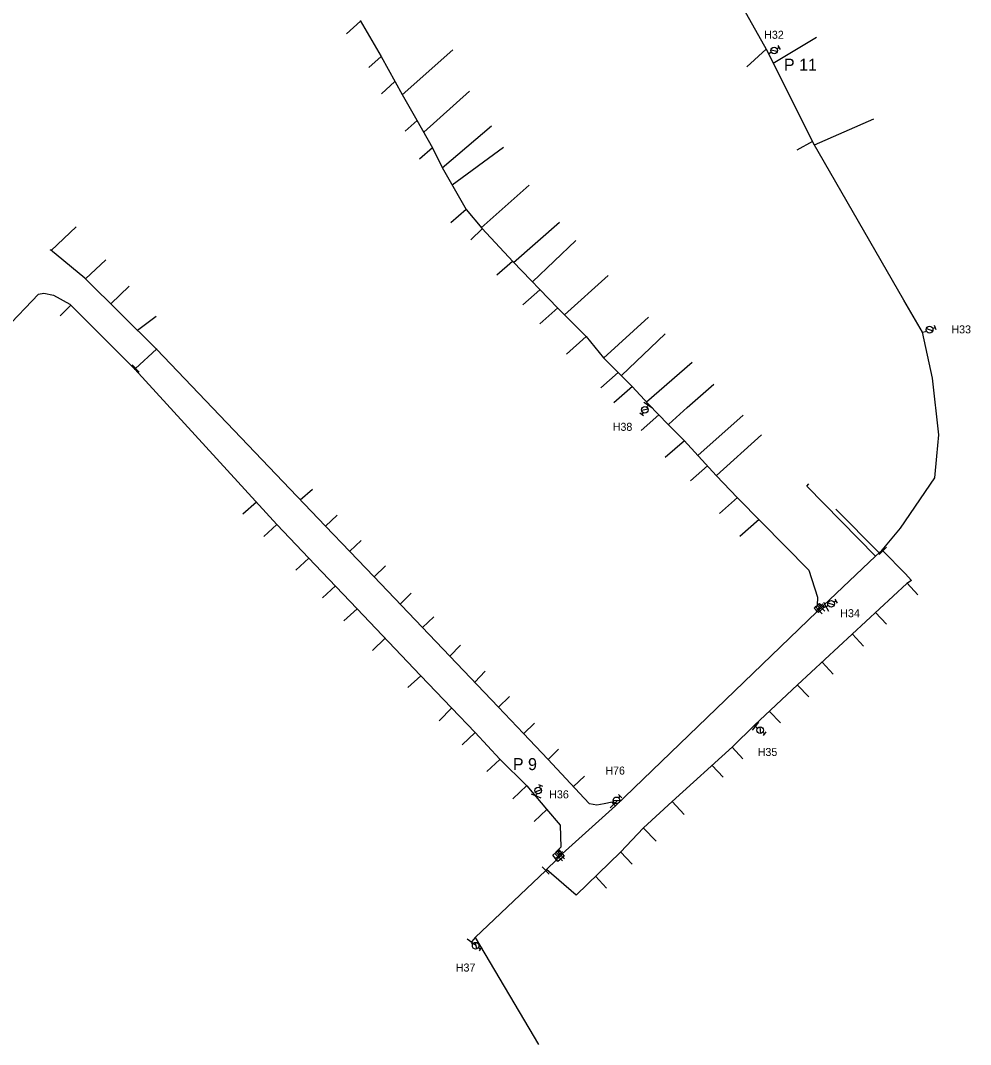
# Model space of a CAD drawing. Extents: x -548873 to -538270, y -1201997 to -1192514.
# Drawn here: x -547306.8 to -547069.3, y -1196073.9 to -1195818 of the extents above; entities that cross this region are included whole.
import ezdxf

# ---------------------------------------------------------------- set-up
doc = ezdxf.new("R2010")
doc.units = 0
for name, color, linetype in [('KN_HRAN_STÁTNÍ', 7, 'Continuous'), ('KN_PARC_Č', 7, 'Continuous'), ('KN_VKP_HRAN_SPORNÁ', 7, 'Continuous'), ('PK_PARC_Čv', 7, 'Continuous'), ('Vrstva 29', 7, 'Continuous'), ('Vrstva 39', 7, 'Continuous')]:
    doc.layers.add(name, color=color, linetype=linetype)

# ---------------------------------------------------------------- blocks, each defined once
blk = doc.blocks.new('147')
at = {"layer": 'KN_HRAN_STÁTNÍ'}
blk.add_line((0, 1.27), (0, -1.27), dxfattribs=at)
blk = doc.blocks.new('160')
at = {"layer": 'KN_HRAN_STÁTNÍ'}
blk.add_circle((0, 0), 0.0458, dxfattribs=at)
blk = doc.blocks.new('133')
at = {"layer": 'KN_HRAN_STÁTNÍ'}
for p, q in [((0.28, 0), (0, 0)), ((0.54, 0.58), (1.7, -0.58)), ((1.94, 0), (2.52, 0)), ((2.52, 0.58), (2.52, -0.58))]:
    blk.add_line(p, q, dxfattribs=at)
blk.add_circle((1.11, 0), 0.825, dxfattribs=at)
blk = doc.blocks.new('150')
at = {"layer": 'KN_HRAN_STÁTNÍ'}
blk.add_line((0, 1.27), (0, -1.27), dxfattribs=at)
blk = doc.blocks.new('124')
at = {"layer": 'KN_HRAN_STÁTNÍ'}
for q in [(-0.19, 1.22), (-0.19, 0.92), (0.19, 1.22), (0, 0), (0.19, 0.92)]:
    blk.add_line((0, 1.07), q, dxfattribs=at)

msp = doc.modelspace()

# ---------------------------------------------------------------- linework, layer by layer
at = {"layer": 'KN_PARC_Č'}
for points in [[(-547221.751, -1195818.177), (-547225.256, -1195821.387)], [(-547118.59, -1195828.738), (-547107.782, -1195822.185)], [(-547211.338, -1195836.652), (-547198.689, -1195825.344)], [(-547120.346, -1195825.246), (-547125.216, -1195829.657)], [(-547216.582, -1195827.05), (-547219.675, -1195829.786)], [(-547213.164, -1195833.313), (-547216.53, -1195836.33)], [(-547205.959, -1195845.978), (-547194.554, -1195835.722)], [(-547207.651, -1195843.016), (-547210.611, -1195845.668)], [(-547201.344, -1195854.82), (-547189.037, -1195844.376)], [(-547108.308, -1195849.144), (-547093.446, -1195842.62)], [(-547203.767, -1195849.817), (-547206.999, -1195852.675)], [(-547198.878, -1195859.084), (-547186.011, -1195849.706)], [(-547108.802, -1195848.244), (-547112.729, -1195850.43)], [(-547191.584, -1195869.809), (-547179.619, -1195859.14)], [(-547195.329, -1195865.222), (-547199.171, -1195868.567)], [(-547299.109, -1195875.503), (-547292.844, -1195869.555)], [(-547191.334, -1195870.095), (-547194.236, -1195872.839)], [(-547183.529, -1195878.482), (-547172.009, -1195868.418)], [(-547178.814, -1195883.336), (-547167.989, -1195872.981)], [(-547290.533, -1195882.56), (-547285.465, -1195877.811)], [(-547183.776, -1195878.223), (-547187.739, -1195881.685)], [(-547170.779, -1195891.567), (-547159.885, -1195881.776)], [(-547284.232, -1195888.79), (-547279.644, -1195884.452)], [(-547176.915, -1195885.291), (-547181.207, -1195889.096)], [(-547294.227, -1195889.127), (-547296.864, -1195891.811)], [(-547172.483, -1195889.853), (-547176.977, -1195893.856)], [(-547277.564, -1195895.384), (-547272.846, -1195891.897)], [(-547161.024, -1195902.36), (-547149.762, -1195892.199)], [(-547165.363, -1195897.012), (-547170.245, -1195901.392)], [(-547156.57, -1195906.759), (-547145.6, -1195896.36)], [(-547150.288, -1195913.312), (-547138.88, -1195903.417)], [(-547157.361, -1195905.978), (-547161.688, -1195909.851)], [(-547153.82, -1195909.475), (-547158.459, -1195913.52)], [(-547144.831, -1195918.962), (-547144.71, -1195918.855), (-547140.082, -1195914.759), (-547133.429, -1195908.88)], [(-547147.201, -1195916.521), (-547151.588, -1195920.467)], [(-547137.419, -1195926.713), (-547126.09, -1195916.673)], [(-547140.81, -1195923.022), (-547145.614, -1195927.251)], [(-547132.807, -1195931.731), (-547121.524, -1195921.515)], [(-547135.05, -1195929.291), (-547139.306, -1195933.032)], [(-547093.021, -1195951.872), (-547110.204, -1195934.346), (-547109.665, -1195933.799)], [(-547236.825, -1195937.781), (-547233.785, -1195935.154)], [(-547247.777, -1195938.381), (-547251.18, -1195941.403)], [(-547127.56, -1195937.196), (-547132.064, -1195941.192)], [(-547230.532, -1195944.374), (-547227.616, -1195941.646)], [(-547092.16, -1195951.056), (-547102.975, -1195940.157)], [(-547242.697, -1195943.93), (-547245.934, -1195946.963)], [(-547122.108, -1195942.735), (-547126.953, -1195946.924)], [(-547224.477, -1195950.633), (-547221.629, -1195947.927)], [(-547234.667, -1195952.324), (-547237.973, -1195955.357)], [(-547218.368, -1195957.015), (-547215.571, -1195954.282)], [(-547228.056, -1195959.275), (-547231.309, -1195962.291)], [(-547085.101, -1195958.617), (-547082.466, -1195961.518)], [(-547211.862, -1195963.835), (-547209.116, -1195961.1)], [(-547222.625, -1195964.996), (-547225.923, -1195968.006)], [(-547206.271, -1195969.698), (-547203.465, -1195967.046)], [(-547093.006, -1195965.938), (-547090.265, -1195968.863)], [(-547215.629, -1195972.345), (-547218.783, -1195975.463)], [(-547098.827, -1195971.342), (-547096.057, -1195974.32)], [(-547199.45, -1195976.849), (-547196.777, -1195974.103)], [(-547106.359, -1195978.335), (-547103.617, -1195981.324)], [(-547206.7, -1195981.723), (-547209.976, -1195984.711)], [(-547193.222, -1195983.379), (-547190.582, -1195980.609)], [(-547112.561, -1195984.094), (-547109.703, -1195987.021)], [(-547187.306, -1195989.582), (-547184.56, -1195986.963)], [(-547198.961, -1195989.794), (-547202.125, -1195992.975)], [(-547119.566, -1195990.633), (-547116.782, -1195993.521)], [(-547180.972, -1195996.193), (-547178.315, -1195993.559)], [(-547193.13, -1195995.901), (-547196.397, -1195999.032)], [(-547174.874, -1196002.666), (-547172.262, -1196000.048)], [(-547128.826, -1195999.552), (-547126.166, -1196002.493)], [(-547186.97, -1196002.624), (-547190.218, -1196005.635)], [(-547133.877, -1196004.12), (-547131.084, -1196007.099)], [(-547168.567, -1196009.398), (-547165.773, -1196006.8)], [(-547180.228, -1196009.198), (-547183.722, -1196012.478)], [(-547143.88, -1196013.166), (-547140.855, -1196016.368)], [(-547175.173, -1196015.159), (-547178.34, -1196018.178)], [(-547151.026, -1196019.776), (-547147.866, -1196023.062)], [(-547156.782, -1196025.759), (-547153.88, -1196028.799)], [(-547172.711, -1196027.633), (-547172.946, -1196027.356), (-547173.034, -1196027.251)], [(-547163.018, -1196031.798), (-547160.246, -1196034.772)], [(-547193.137, -1196047.131), (-547177.251, -1196073.867)]]:
    msp.add_lwpolyline(points, dxfattribs=at)
at = {"layer": 'KN_VKP_HRAN_SPORNÁ'}
for points in [[(-547091.399, -1195950.335), (-547086.803, -1195944.882), (-547078.208, -1195932.264), (-547077.72, -1195926.902), (-547077.231, -1195921.539), (-547078.798, -1195907.393), (-547081.25, -1195895.915), (-547085.993, -1195887.926), (-547108.633, -1195848.58), (-547110.649, -1195844.563), (-547120.307, -1195825.316), (-547132.374, -1195803.704)], [(-547221.839, -1195818.026), (-547216.584, -1195827.046), (-547211.393, -1195836.558), (-547207.675, -1195842.974), (-547203.759, -1195849.831), (-547201.379, -1195854.759), (-547195.331, -1195865.219), (-547191.469, -1195869.95), (-547183.655, -1195878.353), (-547172.5, -1195889.836), (-547165.357, -1195897.018), (-547161.068, -1195902.317), (-547153.83, -1195909.465), (-547149.764, -1195913.881), (-547144.856, -1195918.937), (-547140.89, -1195922.935), (-547132.859, -1195931.676), (-547127.507, -1195937.252), (-547109.671, -1195955.368), (-547107.498, -1195962.08), (-547107.616, -1195964.178), (-547107.081, -1195964.703)], [(-547272.74, -1195900.153), (-547290.68, -1195882.415), (-547299.27, -1195875.371)], [(-547423.899, -1196017.008), (-547412.145, -1196004.69), (-547395.753, -1195987.042), (-547390.663, -1195981.436), (-547374.686, -1195963.838), (-547358.776, -1195946.603), (-547347.545, -1195935.094), (-547330.623, -1195917.023), (-547319.187, -1195904.069), (-547302.312, -1195886.45), (-547300.97, -1195886.17), (-547298.561, -1195886.625), (-547294.438, -1195888.916), (-547286.694, -1195896.655), (-547278.196, -1195905.147)], [(-547272.74, -1195900.153), (-547277.999, -1195904.967)], [(-547158.449, -1196013.812), (-547158.901, -1196013.344), (-547160.905, -1196013.726), (-547162.733, -1196014.074), (-547164.529, -1196013.709), (-547165.839, -1196012.311), (-547174.918, -1196002.619), (-547181.018, -1195996.145), (-547187.366, -1195989.519), (-547218.417, -1195956.963), (-547224.424, -1195950.688), (-547230.562, -1195944.343), (-547237.595, -1195936.974), (-547272.74, -1195900.153)], [(-547277.999, -1195904.967), (-547278.196, -1195905.147)], [(-547278.196, -1195905.147), (-547242.703, -1195943.924), (-547233.072, -1195953.991), (-547222.663, -1195964.956), (-547206.744, -1195981.678), (-547199.004, -1195989.749), (-547193.106, -1195995.926), (-547186.976, -1196002.618), (-547180.21, -1196009.216), (-547175.25, -1196015.067), (-547171.896, -1196019.082), (-547171.717, -1196024.585), (-547172.927, -1196025.787), (-547172.17, -1196026.546)], [(-547091.204, -1195950.533), (-547085.606, -1195956.219), (-547084.044, -1195957.943), (-547085.166, -1195958.659), (-547098.832, -1195971.348), (-547112.499, -1195984.036), (-547123.254, -1195994.076), (-547128.777, -1195999.508), (-547143.908, -1196013.192), (-547151.02, -1196019.769), (-547156.812, -1196025.79), (-547167.902, -1196036.527), (-547175.256, -1196030.173)], [(-547106.575, -1195964.709), (-547106.131, -1195964.293), (-547093.022, -1195951.873), (-547092.158, -1195951.054), (-547091.399, -1195950.335)], [(-547091.399, -1195950.335), (-547091.204, -1195950.533)], [(-547107.234, -1195965.323), (-547106.831, -1195964.948)], [(-547107.081, -1195964.703), (-547106.831, -1195964.948)], [(-547106.831, -1195964.948), (-547106.575, -1195964.709)], [(-547158.06, -1196014.212), (-547107.585, -1195965.65), (-547107.234, -1195965.323)], [(-547171.655, -1196026.565), (-547171.343, -1196026.249), (-547158.06, -1196014.212)], [(-547158.06, -1196014.212), (-547158.449, -1196013.812)], [(-547175.256, -1196030.173), (-547172.781, -1196027.704), (-547172.406, -1196027.325), (-547172.166, -1196027.082)], [(-547172.17, -1196026.546), (-547171.902, -1196026.815)], [(-547172.166, -1196027.082), (-547171.902, -1196026.815)], [(-547171.902, -1196026.815), (-547171.655, -1196026.565)], [(-547175.468, -1196030.371), (-547193.137, -1196047.131), (-547193.944, -1196048.142)], [(-547175.256, -1196030.173), (-547175.468, -1196030.371)]]:
    msp.add_lwpolyline(points, dxfattribs=at)
at = {"layer": 'PK_PARC_Čv'}
for points in [[(-547119.775, -1195826.375), (-547119.337, -1195826.121)], [(-547081.25, -1195895.915), (-547080.578, -1195895.718)], [(-547149.746, -1195913.9), (-547149.873, -1195914.084), (-547150.063, -1195914.36)], [(-547107.05, -1195963.65), (-547105.98, -1195964.7), (-547107.3, -1195965.93), (-547108.37, -1195964.88), (-547107.05, -1195963.65)], [(-547106.131, -1195964.293), (-547105.766, -1195964.646), (-547105.442, -1195964.481), (-547105.136, -1195964.325)], [(-547123.329, -1195994.15), (-547123.087, -1195994.35), (-547122.74, -1195994.638)], [(-547177.954, -1196011.877), (-547177.907, -1196011.768), (-547177.771, -1196011.455)], [(-547158.588, -1196013.668), (-547158.579, -1196013.659)], [(-547173.726, -1196026.578), (-547172.166, -1196025.268), (-547170.88, -1196026.8), (-547172.44, -1196028.11), (-547173.726, -1196026.578)], [(-547193.944, -1196048.142), (-547194.067, -1196048.297), (-547194.154, -1196048.425), (-547193.923, -1196048.577)]]:
    msp.add_lwpolyline(points, dxfattribs=at)

# ---------------------------------------------------------------- block references
for name, p, xscale, yscale, rotation in [('133', (-547119.337, -1195826.121), 1.0000000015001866, 1.0000000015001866, 30.99999982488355), ('133', (-547080.578, -1195895.718), 1.035124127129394, 1.0351241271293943, 22.503654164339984), ('150', (-547149.873, -1195914.084), 0.9999999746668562, 0.999999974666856, 55.999999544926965), ('133', (-547150.063, -1195914.36), 0.9999999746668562, 0.999999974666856, -124.00000045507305), ('133', (-547105.136, -1195964.325), 1.0072562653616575, 1.0072562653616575, 28.76666512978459), ('150', (-547105.442, -1195964.481), 1.0072562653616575, 1.0072562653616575, 28.76666512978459), ('150', (-547123.087, -1195994.35), 1.000000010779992, 1.0000000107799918, -38.9999989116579), ('133', (-547122.74, -1195994.638), 1.000000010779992, 1.0000000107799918, -38.9999989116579), ('133', (-547177.771, -1196011.455), 1.0000000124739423, 1.000000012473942, 67.0000004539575), ('150', (-547177.907, -1196011.768), 1.0000000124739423, 1.000000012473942, 67.0000004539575), ('133', (-547158.579, -1196013.659), 1.0000000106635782, 1.0000000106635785, 45.99999834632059), ('150', (-547194.067, -1196048.297), 1.000000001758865, 1.000000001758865, -125.99999933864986), ('133', (-547193.923, -1196048.577), 0.9999999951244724, 0.9999999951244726, -33.000001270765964)]:
    msp.add_blockref(name, p, dxfattribs=dict(at, xscale=xscale, yscale=yscale, rotation=rotation))
at = {"layer": 'Vrstva 29'}
for name, p, xscale, yscale, rotation in [('160', (-547299.27, -1195875.371), 1.000000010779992, 1.0000000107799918, -38.9999989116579), ('160', (-547272.74, -1195900.153), 1.000000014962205, 1.0000000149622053, 179.0000000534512), ('147', (-547277.999, -1195904.967), 1.00000000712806, 1.00000000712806, -136.99999943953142), ('160', (-547278.196, -1195905.147), 1.00000001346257, 1.0000000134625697, 88.00000009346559), ('147', (-547091.204, -1195950.533), 0.999999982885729, 0.9999999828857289, -45), ('160', (-547091.399, -1195950.335), 0.9999999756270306, 0.9999999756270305, -86.99999998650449), ('147', (-547107.234, -1195965.323), 1.00000000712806, 1.00000000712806, -136.99999943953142), ('147', (-547107.081, -1195964.703), 1.0000000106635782, 1.0000000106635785, 135.99999834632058), ('147', (-547106.575, -1195964.709), 1.0000000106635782, 1.0000000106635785, -135.99999834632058), ('160', (-547106.831, -1195964.948), 1.0000000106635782, 1.0000000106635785, -135.99999834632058), ('147', (-547158.449, -1196013.812), 0.999999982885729, 0.9999999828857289, 135), ('147', (-547172.166, -1196027.082), 1.0000000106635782, 1.0000000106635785, 45.99999834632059), ('147', (-547172.17, -1196026.546), 0.999999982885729, 0.9999999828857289, 135), ('147', (-547171.655, -1196026.565), 1.0000000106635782, 1.0000000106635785, -134.00000165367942), ('160', (-547171.902, -1196026.815), 1.0000000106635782, 1.0000000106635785, -134.00000165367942), ('147', (-547175.468, -1196030.371), 1.0000000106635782, 1.0000000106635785, -135.99999834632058), ('160', (-547175.256, -1196030.173), 0.9999999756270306, 0.9999999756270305, 93.00000001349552), ('160', (-547193.944, -1196048.142), 1.000000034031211, 1.0000000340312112, 51.999999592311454)]:
    msp.add_blockref(name, p, dxfattribs=dict(at, xscale=xscale, yscale=yscale, rotation=rotation))
at = {"layer": 'Vrstva 29', "rotation": 180}
msp.add_blockref('160', (-547158.06, -1196014.212), dxfattribs=at)
at = {"layer": 'Vrstva 39'}
msp.add_blockref('124', (-547172.17, -1196026.546), dxfattribs=at)

# ---------------------------------------------------------------- texts
at = {"layer": 'PK_PARC_Čv'}
for s, height, p in [('H32', 2, (-547120.867, -1195822.611)), ('P 11', 3, (-547115.927, -1195830.591)), ('H33', 2, (-547074.068, -1195896.208)), ('H38', 2, (-547158.733, -1195920.55)), ('H34', 2, (-547101.846, -1195967.115)), ('H35', 2, (-547122.49, -1196001.778)), ('P 9', 3, (-547183.691, -1196005.315)), ('H76', 2, (-547160.579, -1196006.429)), ('H36', 2, (-547174.611, -1196012.365)), ('H37', 2, (-547197.963, -1196055.637))]:
    msp.add_text(s, height=height, dxfattribs=at).set_placement(p)

doc.saveas('drawing.dxf')
